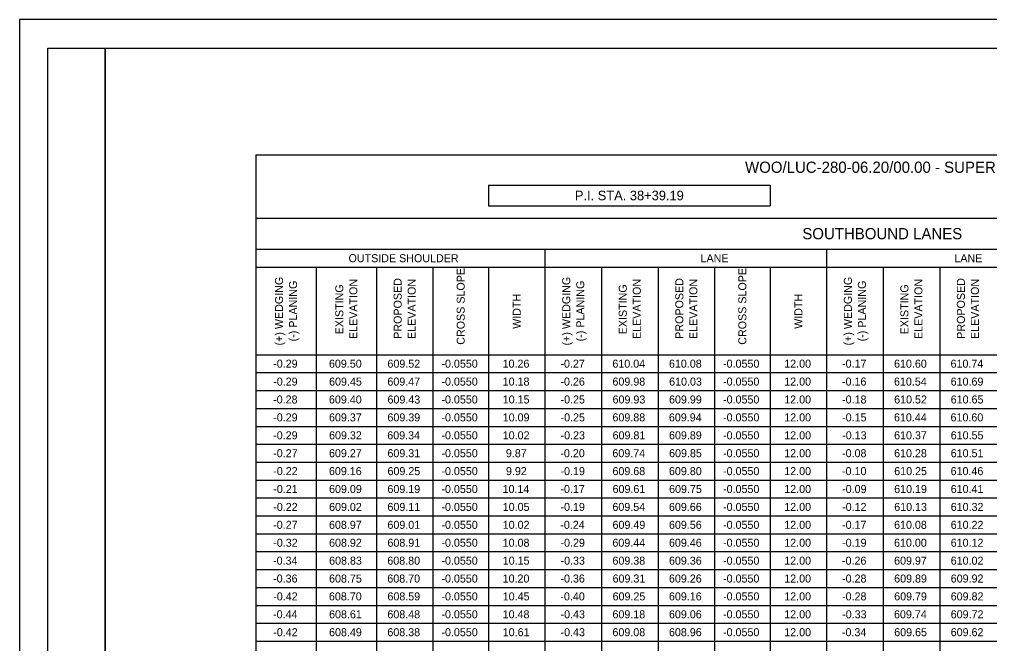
# Model space of a CAD drawing. Extents: x 0 to 34, y 0 to 22.
# Drawn here: x 0 to 16.97, y 11.09 to 22 of the extents above; entities that cross this region are included whole.
import ezdxf

# ---------------------------------------------------------------- set-up
doc = ezdxf.new("R2010")
doc.units = 0
for name, color, linetype in [('Default', 7, 'Continuous'), ('SH_Border', 7, 'Continuous'), ('SH_Cut_Line', 7, 'Continuous')]:
    doc.layers.add(name, color=color, linetype=linetype)

msp = doc.modelspace()

# ---------------------------------------------------------------- linework, layer by layer
at = {"layer": 'Default'}
for p, q in [((4.135, 19.63), (29.368, 19.63)), ((4.135, 19.63), (4.135, 2.369)), ((8.203, 19.103), (13.128, 19.103)), ((8.203, 19.103), (8.203, 18.741)), ((13.128, 19.103), (13.128, 18.741)), ((8.203, 18.741), (13.128, 18.741)), ((4.135, 18.526), (29.368, 18.526)), ((4.135, 17.983), (29.368, 17.983)), ((9.191, 17.983), (9.191, 2.369)), ((14.116, 17.983), (14.116, 2.369)), ((4.135, 17.67), (24.954, 17.67)), ((5.189, 17.67), (5.189, 2.369)), ((6.243, 17.67), (6.243, 2.369)), ((7.231, 17.67), (7.231, 2.369)), ((8.203, 17.67), (8.203, 2.369)), ((10.18, 17.67), (10.18, 2.369)), ((11.168, 17.67), (11.168, 2.369)), ((12.156, 17.67), (12.156, 2.369)), ((13.128, 17.67), (13.128, 2.369)), ((15.104, 17.67), (15.104, 2.369)), ((16.093, 17.67), (16.093, 2.369)), ((4.135, 16.138), (29.368, 16.138)), ((4.135, 15.825), (29.368, 15.825)), ((4.135, 15.512), (29.368, 15.512)), ((4.135, 15.199), (29.368, 15.199)), ((4.135, 14.886), (29.368, 14.886)), ((4.135, 14.574), (29.368, 14.574)), ((4.135, 14.261), (29.368, 14.261)), ((4.135, 13.948), (29.368, 13.948)), ((4.135, 13.635), (29.368, 13.635)), ((4.135, 13.322), (29.368, 13.322)), ((4.135, 13.009), (29.368, 13.009)), ((4.135, 12.696), (29.368, 12.696)), ((4.135, 12.383), (29.368, 12.383)), ((4.135, 12.07), (29.368, 12.07)), ((4.135, 11.757), (29.368, 11.757)), ((4.135, 11.444), (29.368, 11.444)), ((4.135, 11.131), (29.368, 11.131))]:
    msp.add_line(p, q, dxfattribs=at)
at = {"layer": 'SH_Border'}
for points in [[(0.5, 21.5), (1.5, 21.5), (1.5, 0.5), (0.5, 0.5)], [(1.5, 21.5), (33.5, 21.5), (33.5, 0.5), (1.5, 0.5)]]:
    msp.add_lwpolyline(points, close=True, dxfattribs=at)
at = {"layer": 'SH_Cut_Line'}
msp.add_lwpolyline([(0, 0), (34, 0), (34, 22), (0, 22)], close=True, dxfattribs=at)

# ---------------------------------------------------------------- texts
at = {"layer": 'Default'}
for s, height, p in [('WOO/LUC-280-06.20/00.00 - SUPERELEVATION TABLE', 0.196, (12.689, 19.318)), ('P.I. STA. 38+39.19', 0.168, (9.714, 18.838)), ('SOUTHBOUND LANES', 0.196, (13.691, 18.157)), ('OUTSIDE SHOULDER', 0.14, (5.756, 17.756)), ('LANE', 0.14, (11.911, 17.756)), ('LANE', 0.14, (16.35, 17.756)), ('-0.29', 0.14, (4.438, 15.912)), ('609.50', 0.14, (5.413, 15.912)), ('609.52', 0.14, (6.436, 15.912)), ('-0.0550', 0.14, (7.38, 15.912)), ('10.26', 0.14, (8.45, 15.912)), ('-0.27', 0.14, (9.461, 15.912)), ('610.04', 0.14, (10.37, 15.912)), ('610.08', 0.14, (11.359, 15.912)), ('-0.0550', 0.14, (12.305, 15.912)), ('12.00', 0.14, (13.375, 15.912)), ('-0.17', 0.14, (14.386, 15.912)), ('610.60', 0.14, (15.295, 15.912)), ('610.74', 0.14, (16.283, 15.912)), ('-0.29', 0.14, (4.438, 15.599)), ('609.45', 0.14, (5.415, 15.599)), ('609.47', 0.14, (6.435, 15.599)), ('-0.0550', 0.14, (7.38, 15.599)), ('10.18', 0.14, (8.451, 15.599)), ('-0.26', 0.14, (9.461, 15.599)), ('609.98', 0.14, (10.371, 15.599)), ('610.03', 0.14, (11.362, 15.599)), ('-0.0550', 0.14, (12.305, 15.599)), ('12.00', 0.14, (13.375, 15.599)), ('-0.16', 0.14, (14.385, 15.599)), ('610.54', 0.14, (15.294, 15.599)), ('610.69', 0.14, (16.285, 15.599)), ('-0.28', 0.14, (4.437, 15.286)), ('609.40', 0.14, (5.413, 15.286)), ('609.43', 0.14, (6.437, 15.286)), ('-0.0550', 0.14, (7.38, 15.286)), ('10.15', 0.14, (8.452, 15.286)), ('-0.25', 0.14, (9.463, 15.286)), ('609.93', 0.14, (10.373, 15.286)), ('609.99', 0.14, (11.36, 15.286)), ('-0.0550', 0.14, (12.305, 15.286)), ('12.00', 0.14, (13.375, 15.286)), ('-0.18', 0.14, (14.386, 15.286)), ('610.52', 0.14, (15.297, 15.286)), ('610.65', 0.14, (16.286, 15.286)), ('-0.29', 0.14, (4.438, 14.973)), ('609.37', 0.14, (5.414, 14.973)), ('609.39', 0.14, (6.436, 14.973)), ('-0.0550', 0.14, (7.38, 14.973)), ('10.09', 0.14, (8.452, 14.973)), ('-0.25', 0.14, (9.463, 14.973)), ('609.88', 0.14, (10.371, 14.973)), ('609.94', 0.14, (11.358, 14.973)), ('-0.0550', 0.14, (12.305, 14.973)), ('12.00', 0.14, (13.375, 14.973)), ('-0.15', 0.14, (14.387, 14.973)), ('610.44', 0.14, (15.294, 14.973)), ('610.60', 0.14, (16.283, 14.973)), ('-0.29', 0.14, (4.438, 14.66)), ('609.32', 0.14, (5.415, 14.66)), ('609.34', 0.14, (6.433, 14.66)), ('-0.0550', 0.14, (7.38, 14.66)), ('10.02', 0.14, (8.452, 14.66)), ('-0.23', 0.14, (9.463, 14.66)), ('609.81', 0.14, (10.373, 14.66)), ('609.89', 0.14, (11.36, 14.66)), ('-0.0550', 0.14, (12.305, 14.66)), ('12.00', 0.14, (13.375, 14.66)), ('-0.13', 0.14, (14.388, 14.66)), ('610.37', 0.14, (15.296, 14.66)), ('610.55', 0.14, (16.286, 14.66)), ('-0.27', 0.14, (4.438, 14.347)), ('609.27', 0.14, (5.414, 14.347)), ('609.31', 0.14, (6.436, 14.347)), ('-0.0550', 0.14, (7.38, 14.347)), ('9.87', 0.14, (8.507, 14.347)), ('-0.20', 0.14, (9.46, 14.347)), ('609.74', 0.14, (10.37, 14.347)), ('609.85', 0.14, (11.361, 14.347)), ('-0.0550', 0.14, (12.305, 14.347)), ('12.00', 0.14, (13.375, 14.347)), ('-0.08', 0.14, (14.386, 14.347)), ('610.28', 0.14, (15.296, 14.347)), ('610.51', 0.14, (16.286, 14.347)), ('-0.22', 0.14, (4.439, 14.034)), ('609.16', 0.14, (5.413, 14.034)), ('609.25', 0.14, (6.437, 14.034)), ('-0.0550', 0.14, (7.38, 14.034)), ('9.92', 0.14, (8.508, 14.034)), ('-0.19', 0.14, (9.462, 14.034)), ('609.68', 0.14, (10.371, 14.034)), ('609.80', 0.14, (11.359, 14.034)), ('-0.0550', 0.14, (12.305, 14.034)), ('12.00', 0.14, (13.375, 14.034)), ('-0.10', 0.14, (14.385, 14.034)), ('610.25', 0.14, (15.298, 14.034)), ('610.46', 0.14, (16.284, 14.034)), ('-0.21', 0.14, (4.439, 13.721)), ('609.09', 0.14, (5.415, 13.721)), ('609.19', 0.14, (6.436, 13.721)), ('-0.0550', 0.14, (7.38, 13.721)), ('10.14', 0.14, (8.449, 13.721)), ('-0.17', 0.14, (9.461, 13.721)), ('609.61', 0.14, (10.373, 13.721)), ('609.75', 0.14, (11.361, 13.721)), ('-0.0550', 0.14, (12.305, 13.721)), ('12.00', 0.14, (13.375, 13.721)), ('-0.09', 0.14, (14.387, 13.721)), ('610.19', 0.14, (15.297, 13.721)), ('610.41', 0.14, (16.286, 13.721)), ('-0.22', 0.14, (4.439, 13.408)), ('609.02', 0.14, (5.415, 13.408)), ('609.11', 0.14, (6.436, 13.408)), ('-0.0550', 0.14, (7.38, 13.408)), ('10.05', 0.14, (8.452, 13.408)), ('-0.19', 0.14, (9.462, 13.408)), ('609.54', 0.14, (10.37, 13.408)), ('609.66', 0.14, (11.359, 13.408)), ('-0.0550', 0.14, (12.305, 13.408)), ('12.00', 0.14, (13.375, 13.408)), ('-0.12', 0.14, (14.387, 13.408)), ('610.13', 0.14, (15.298, 13.408)), ('610.32', 0.14, (16.286, 13.408)), ('-0.27', 0.14, (4.438, 13.095)), ('608.97', 0.14, (5.414, 13.095)), ('609.01', 0.14, (6.436, 13.095)), ('-0.0550', 0.14, (7.38, 13.095)), ('10.02', 0.14, (8.452, 13.095)), ('-0.24', 0.14, (9.459, 13.095)), ('609.49', 0.14, (10.372, 13.095)), ('609.56', 0.14, (11.359, 13.095)), ('-0.0550', 0.14, (12.305, 13.095)), ('12.00', 0.14, (13.375, 13.095)), ('-0.17', 0.14, (14.386, 13.095)), ('610.08', 0.14, (15.296, 13.095)), ('610.22', 0.14, (16.286, 13.095)), ('-0.32', 0.14, (4.439, 12.782)), ('608.92', 0.14, (5.415, 12.782)), ('608.91', 0.14, (6.436, 12.782)), ('-0.0550', 0.14, (7.38, 12.782)), ('10.08', 0.14, (8.451, 12.782)), ('-0.29', 0.14, (9.462, 12.782)), ('609.44', 0.14, (10.37, 12.782)), ('609.46', 0.14, (11.359, 12.782)), ('-0.0550', 0.14, (12.305, 12.782)), ('12.00', 0.14, (13.375, 12.782)), ('-0.19', 0.14, (14.387, 12.782)), ('610.00', 0.14, (15.295, 12.782)), ('610.12', 0.14, (16.286, 12.782)), ('-0.34', 0.14, (4.436, 12.469)), ('608.83', 0.14, (5.416, 12.469)), ('608.80', 0.14, (6.434, 12.469)), ('-0.0550', 0.14, (7.38, 12.469)), ('10.15', 0.14, (8.452, 12.469)), ('-0.33', 0.14, (9.463, 12.469)), ('609.38', 0.14, (10.371, 12.469)), ('609.36', 0.14, (11.359, 12.469)), ('-0.0550', 0.14, (12.305, 12.469)), ('12.00', 0.14, (13.375, 12.469)), ('-0.26', 0.14, (14.385, 12.469)), ('609.97', 0.14, (15.296, 12.469)), ('610.02', 0.14, (16.286, 12.469)), ('-0.36', 0.14, (4.437, 12.156)), ('608.75', 0.14, (5.415, 12.156)), ('608.70', 0.14, (6.434, 12.156)), ('-0.0550', 0.14, (7.38, 12.156)), ('10.20', 0.14, (8.45, 12.156)), ('-0.36', 0.14, (9.461, 12.156)), ('609.31', 0.14, (10.373, 12.156)), ('609.26', 0.14, (11.359, 12.156)), ('-0.0550', 0.14, (12.305, 12.156)), ('12.00', 0.14, (13.375, 12.156)), ('-0.28', 0.14, (14.386, 12.156)), ('609.89', 0.14, (15.297, 12.156)), ('609.92', 0.14, (16.286, 12.156)), ('-0.42', 0.14, (4.439, 11.844)), ('608.70', 0.14, (5.413, 11.844)), ('608.59', 0.14, (6.436, 11.844)), ('-0.0550', 0.14, (7.38, 11.844)), ('10.45', 0.14, (8.452, 11.844)), ('-0.40', 0.14, (9.46, 11.844)), ('609.25', 0.14, (10.373, 11.844)), ('609.16', 0.14, (11.359, 11.844)), ('-0.0550', 0.14, (12.305, 11.844)), ('12.00', 0.14, (13.375, 11.844)), ('-0.28', 0.14, (14.386, 11.844)), ('609.79', 0.14, (15.297, 11.844)), ('609.82', 0.14, (16.286, 11.844)), ('-0.44', 0.14, (4.436, 11.531)), ('608.61', 0.14, (5.415, 11.531)), ('608.48', 0.14, (6.435, 11.531)), ('-0.0550', 0.14, (7.38, 11.531)), ('10.48', 0.14, (8.451, 11.531)), ('-0.43', 0.14, (9.463, 11.531)), ('609.18', 0.14, (10.371, 11.531)), ('609.06', 0.14, (11.359, 11.531)), ('-0.0550', 0.14, (12.305, 11.531)), ('12.00', 0.14, (13.375, 11.531)), ('-0.33', 0.14, (14.388, 11.531)), ('609.74', 0.14, (15.294, 11.531)), ('609.72', 0.14, (16.286, 11.531)), ('-0.42', 0.14, (4.439, 11.218)), ('608.49', 0.14, (5.415, 11.218)), ('608.38', 0.14, (6.435, 11.218)), ('-0.0550', 0.14, (7.38, 11.218)), ('10.61', 0.14, (8.452, 11.218)), ('-0.43', 0.14, (9.463, 11.218)), ('609.08', 0.14, (10.371, 11.218)), ('608.96', 0.14, (11.359, 11.218)), ('-0.0550', 0.14, (12.305, 11.218)), ('12.00', 0.14, (13.375, 11.218)), ('-0.34', 0.14, (14.384, 11.218)), ('609.65', 0.14, (15.298, 11.218)), ('609.62', 0.14, (16.286, 11.218))]:
    msp.add_text(s, height=height, dxfattribs=at).set_placement(p)
for s, p in [('CROSS SLOPE', (7.787, 16.313)), ('CROSS SLOPE', (12.712, 16.313)), ('(+) WEDGING', (4.61, 16.3)), ('(+) WEDGING', (9.633, 16.3)), ('(+) WEDGING', (14.558, 16.3)), ('(-) PLANING', (4.855, 16.372)), ('EXISTING ', (5.664, 16.495)), ('ELEVATION', (5.909, 16.413)), ('PROPOSED ', (6.685, 16.417)), ('ELEVATION', (6.93, 16.413)), ('(-) PLANING', (9.878, 16.372)), ('EXISTING ', (10.621, 16.495)), ('ELEVATION', (10.866, 16.413)), ('PROPOSED ', (11.61, 16.417)), ('ELEVATION', (11.855, 16.413)), ('(-) PLANING', (14.803, 16.372)), ('EXISTING ', (15.546, 16.495)), ('ELEVATION', (15.791, 16.413)), ('PROPOSED ', (16.534, 16.417)), ('ELEVATION', (16.779, 16.413)), ('WIDTH', (8.767, 16.591)), ('WIDTH', (13.692, 16.591))]:
    msp.add_text(s, height=0.14, rotation=90, dxfattribs=at).set_placement(p)

doc.saveas('drawing.dxf')
